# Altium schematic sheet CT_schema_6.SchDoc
size 255 x 245 mm
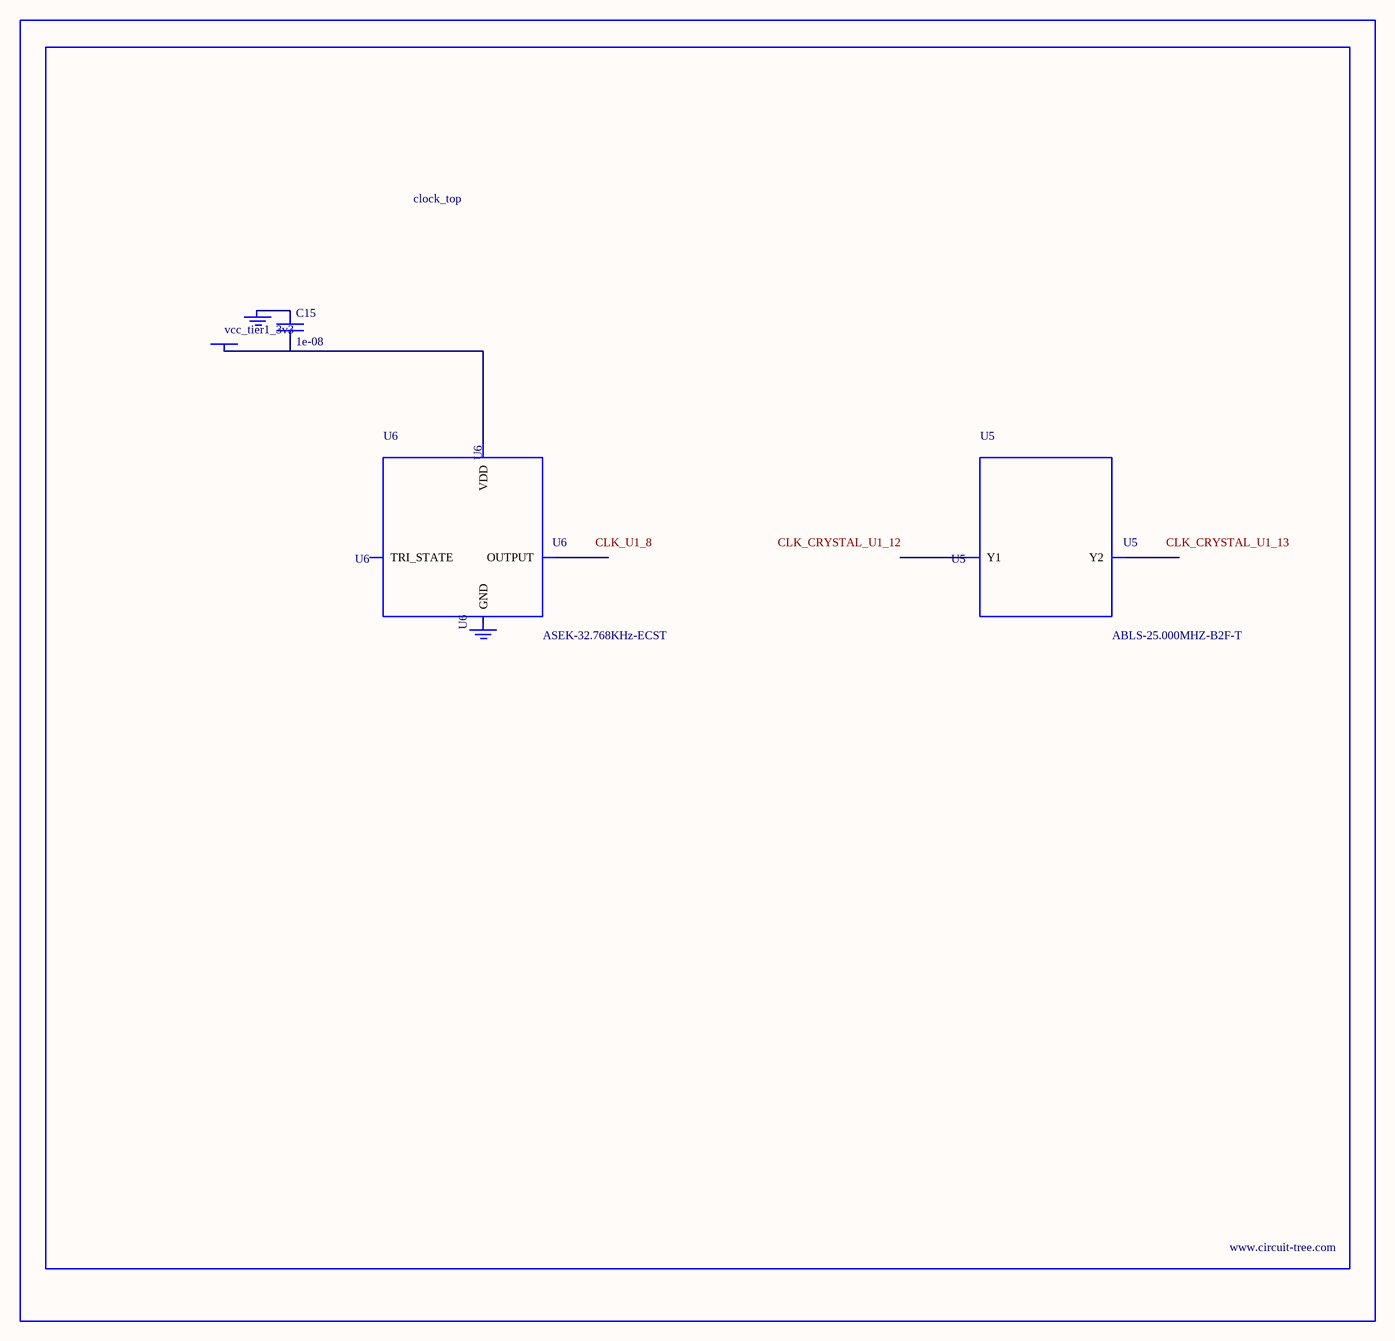
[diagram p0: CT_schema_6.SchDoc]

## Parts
BORDER5  (no value)
C15  1e-08  [C0402]
GND_INSTANCE_5_0  (no value)
GND_INSTANCE_5_1  (no value)
POWER_INSTANCE_5_0  vcc_tier1_3v3
U5  ABLS-25.000MHZ-B2F-T  [ABLS-25.000MHZ-B2F-T]
U6  ASEK-32.768KHz-ECST  [ASEK]

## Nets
NetC15_1: C15.1 GND_INSTANCE_5_0.0(GND)
NetC15_2: C15.2 POWER_INSTANCE_5_0.0(PWR) U6.4(VDD)

Not connected (* = marked no-connect by the designer): GND_INSTANCE_5_1 0(GND); U5 1(Y1) 2(Y2); U6 1(TRI_STATE) 2(GND) 3(OUTPUT)

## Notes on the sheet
- Labels drawn without touching a wire or pin: CLK_CRYSTAL_U1_12, CLK_CRYSTAL_U1_13, CLK_U1_8

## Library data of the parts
BORDER5 = BORDER_PAGE5
C15 = C0402C103K3RAC
GND_INSTANCE_5_0 GND_INSTANCE_5_1 = GND
POWER_INSTANCE_5_0 = PWR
